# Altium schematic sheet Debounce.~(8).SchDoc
size A4
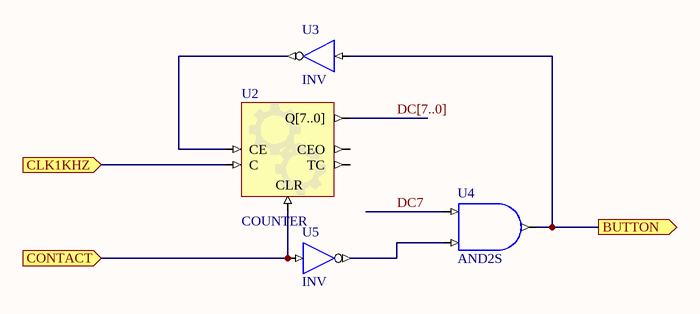
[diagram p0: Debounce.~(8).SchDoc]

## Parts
U2  COUNTER
U3  INV
U4  AND2S
U5  INV

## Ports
BUTTON (out), CLK1KHZ (in), CONTACT (in)

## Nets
BUTTON: U3.I U4.O ; port BUTTON
CLK1KHZ: U2.C ; port CLK1KHZ
CONTACT: U2.CLR U5.I ; port CONTACT
DC7: U4.I0
NetU2_CE: U2.CE U3.O
NetU4_I1: U4.I1 U5.O

Not connected (* = marked no-connect by the designer): U2 CEO Q[7..0] TC

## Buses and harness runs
bus DC[7..0]

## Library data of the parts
U2 = COUNTER: Configurable Counter; ConfiguratorName: GENERIC_COUNTER; ConfigurationParameters: {}Version[1.0]{}Type[Binary]{}SyncReset[False]{}NegativeClockEdge[False]{}FixedDirection[True]{}IsIncrement[True]{}SignalWidth[8]{}MaxValue[255]{}BusOutput[True]{}Loadable[False]{}BusInput[False]{}
U3 U5 = INV: Inverter; FunctionalClass: Logic Primitive; ArchiveName: GENERIC; VHDLIB_SIM: GENERIC_LIB
U4 = AND2S: 2-Input AND Gate, Single Pin Version; XilinxEquivalent: AND2; FunctionalClass: Logic Primitive; PortSize: 2; ArchiveName: GENERIC; VHDLIB_SIM: GENERIC_LIB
